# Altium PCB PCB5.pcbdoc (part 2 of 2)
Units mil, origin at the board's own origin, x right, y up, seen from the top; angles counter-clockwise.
Board outline 1951.69 x 1930.99 mil, 2 copper layers (Top Layer, Bottom Layer); 57 components, 38 nets, 209 pads, 95 vias.
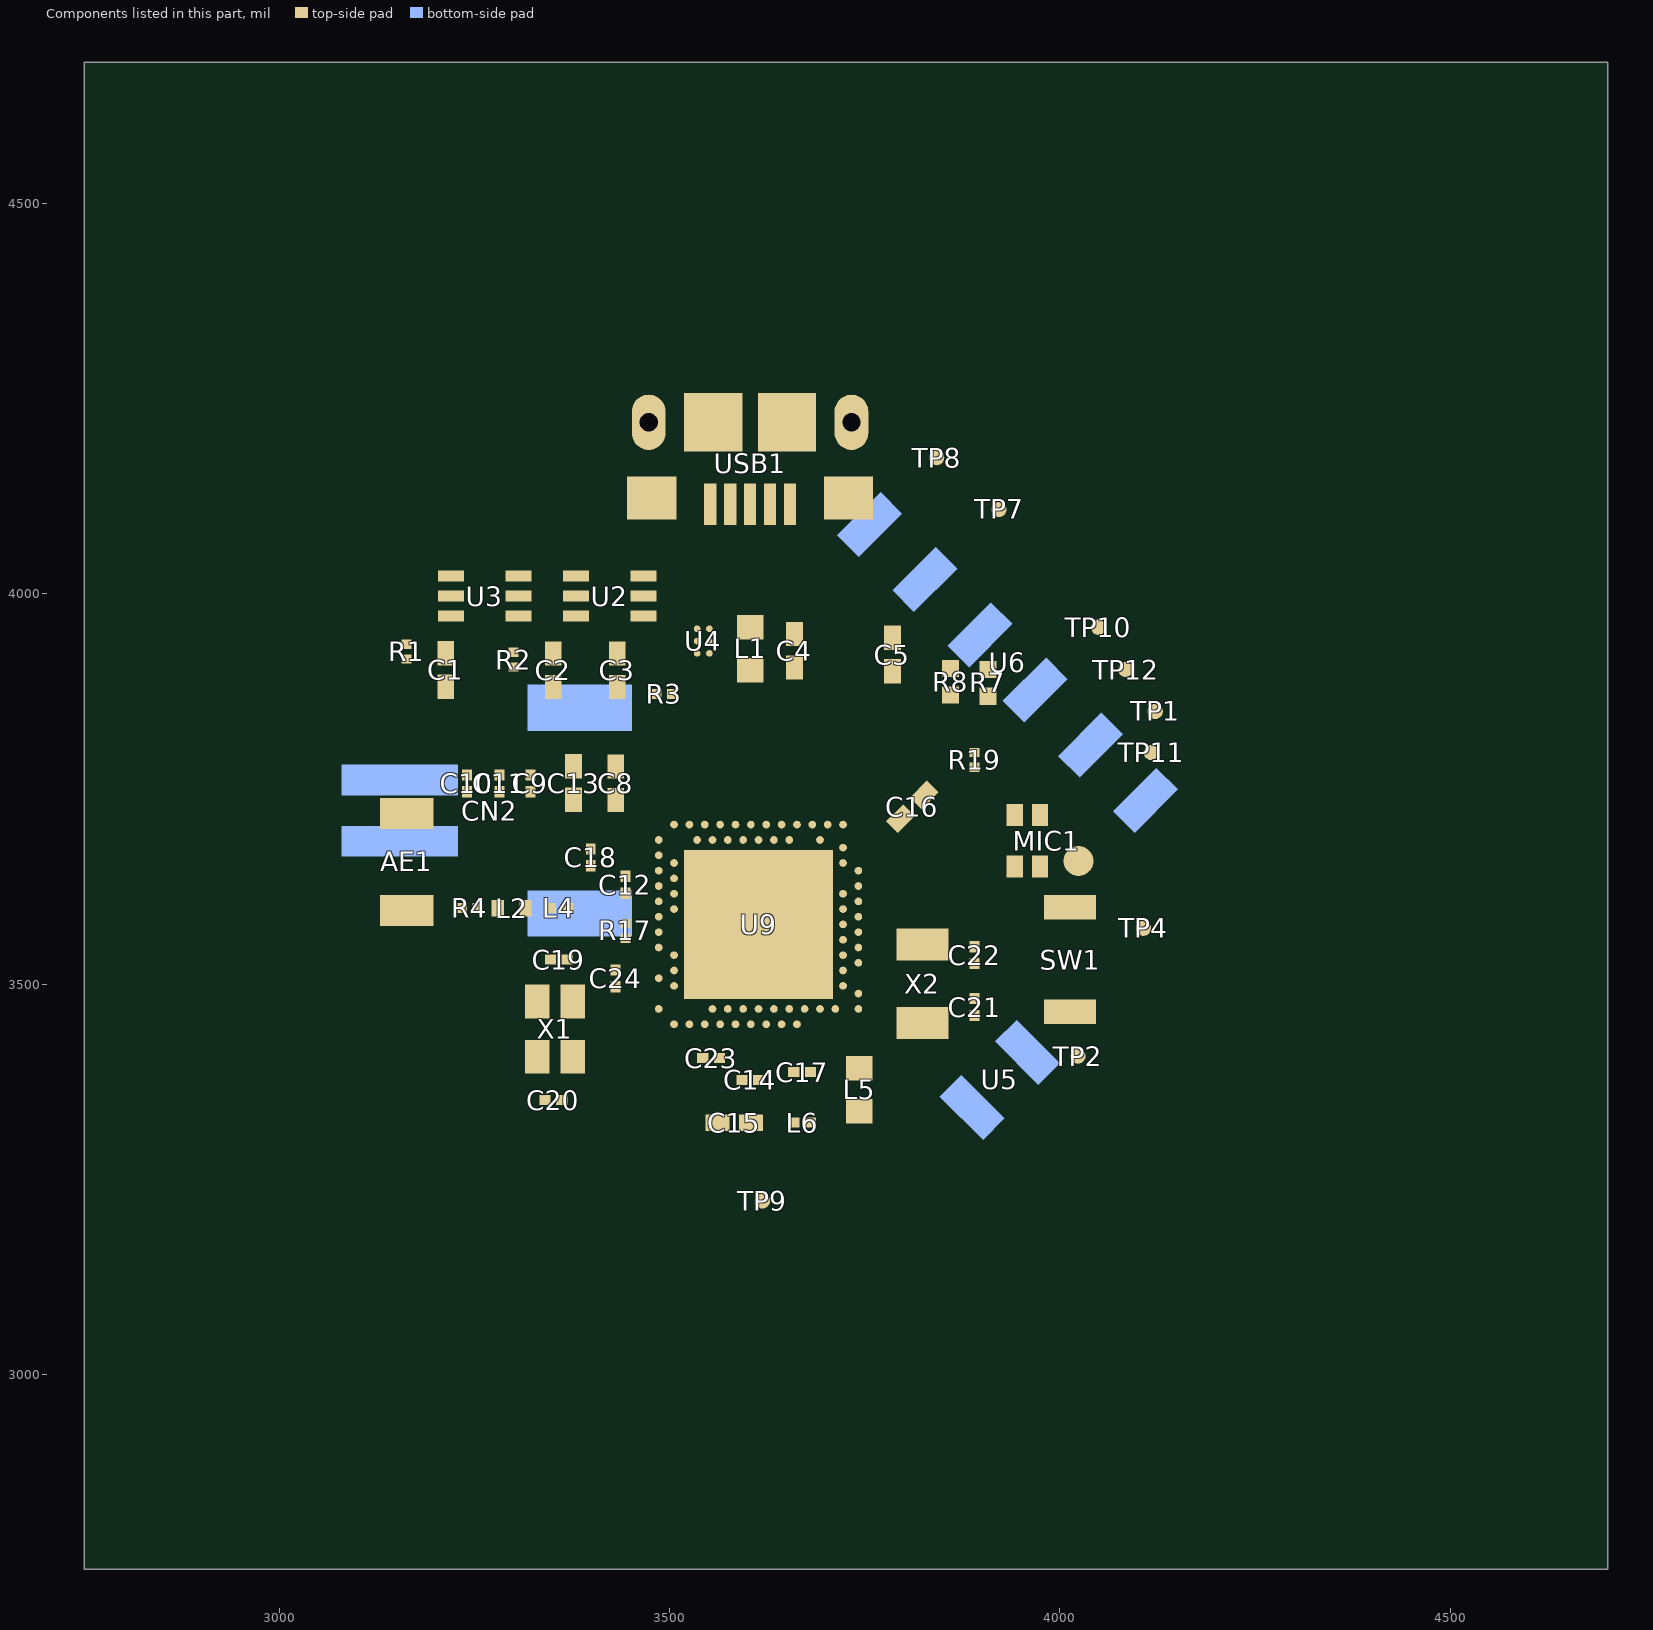
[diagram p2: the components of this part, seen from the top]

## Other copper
Top Layer:
  region net VBUS: 3651.17,4079.14 3657.08,4079.14 cw(c3668.15,4079.14) 3661.51,4088 3646.74,4088 cw(c3640.1,4079.14)
  region net $1N2608: 3443.52,4024.83 3443.52,4020.83 cw(c3443.52,4013.33) 3449.52,4017.83 3449.52,4027.83 cw(c3443.52,4032.33)
  region net $1N2608: 3304.25,3958.76 3308.25,3958.76 cw(c3315.75,3958.76) 3311.25,3964.76 3301.25,3964.76 cw(c3296.75,3958.76)
  region net $1N15802: 3285.28,4017.41 3285.28,4011.75 cw(c3295.74,4001.29) 3293.71,4015.94 3289.52,4025.89 cw(c3274.67,4028.01)
  region net $1N15802: 3175.32,3933.57 3175.32,3937.57 cw(c3175.32,3945.07) 3169.32,3940.57 3169.32,3930.57 cw(c3175.32,3926.07)
  region net $1N15802: 3227.82,3936.11 3227.82,3941.77 cw(c3222.46,3947.12) 3221.43,3939.62 3223.57,3927.63 cw(c3238.42,3925.5)
  region net $1N2608: 3312.3,3923.33 3312.3,3927.33 cw(c3312.3,3934.83) 3306.3,3930.33 3306.3,3920.33 cw(c3312.3,3915.83)
  region net $1N2608: 3307.67,3930.26 3304.84,3933.08 cw(c3300.18,3937.74) 3298.81,3931.3 3306.3,3924.64 cw(c3311.61,3926.32)
  region net $1N2608: 3367.56,3920.24 3367.56,3924.24 cw(c3367.56,3931.74) 3361.56,3927.24 3361.56,3917.24 cw(c3367.56,3912.74)
  region net $1N2608: 3334.3,3927.33 3334.3,3923.33 cw(c3334.3,3915.83) 3340.3,3920.33 3340.3,3930.33 cw(c3334.3,3934.83)
  region: 3449.57,3921.7 3449.57,3925.7 cw(c3449.57,3933.2) 3443.57,3928.7 3443.57,3918.7 cw(c3449.57,3914.2)
  region net +3V3: 3626.98,3899.79 3626.98,3904.48 cw(c3626.98,3913.26) 3619.95,3907.99 3619.95,3896.28 cw(c3626.98,3891.01)
  region net +3V3: 3585.11,3924.15 3579.67,3921.23 cw(c3564.01,3905.57) 3585.94,3908.7 3597.64,3917.88 cw(c3600.77,3939.81)
  region net LX: 3585.78,3977.23 3581.69,3975.67 cw(c3571.09,3965.06) 3585.94,3967.18 3594.27,3972.99 cw(c3596.39,3987.84)
  region net +3V3: 3642.18,3904.48 3642.18,3899.79 cw(c3642.18,3891.01) 3649.21,3896.28 3649.21,3907.99 cw(c3642.18,3913.26)
  region net +3V3: 3679.33,3902.83 3679.33,3908.74 cw(c3679.33,3919.81) 3670.47,3913.17 3670.47,3898.4 cw(c3679.33,3891.76)
  region net $1N3382: 3203.39,3595.24 3203.39,3599.24 cw(c3203.39,3606.74) 3197.39,3602.24 3197.39,3592.24 cw(c3203.39,3587.74)
  region net $1N3382: 3222.07,3599.24 3222.07,3595.24 cw(c3222.07,3587.74) 3228.07,3592.24 3228.07,3602.24 cw(c3222.07,3606.74)
  region net $1N5000: 3265.03,3595.24 3265.03,3599.24 cw(c3265.03,3606.74) 3259.03,3602.24 3259.03,3592.24 cw(c3265.03,3587.74)
  region net $1N5000: 3265.81,3599.24 3265.81,3595.24 cw(c3265.81,3587.74) 3271.81,3592.24 3271.81,3602.24 cw(c3265.81,3606.74)
  region net ANT: 3328.99,3595.24 3328.99,3599.24 cw(c3328.99,3606.74) 3322.99,3602.24 3322.99,3592.24 cw(c3328.99,3587.74)
  region net +3V3: 3890.12,3906.81 3890.12,3902.13 cw(c3890.12,3893.34) 3897.15,3898.61 3897.15,3910.33 cw(c3890.12,3915.6)
  region net +3V3: 3920.57,3887 3923.38,3890.81 cw(c3935.8,3903.24) 3918.41,3900.75 3910.64,3891.96 cw(c3908.15,3874.57)
  region net VDDH: 3842.11,3872.73 3842.11,3868.05 cw(c3842.11,3859.26) 3849.14,3864.53 3849.14,3876.25 cw(c3842.11,3881.52)
  region net +3V3: 3862.11,3920.42 3857.42,3920.42 cw(c3852.37,3920.42) 3853.91,3915.61 3865.62,3915.61 cw(c3867.17,3920.42)
  region net +3V3: 3877.42,3902.13 3877.42,3906.81 cw(c3877.42,3915.6) 3870.4,3910.33 3870.4,3898.61 cw(c3877.42,3893.34)
  region net VDD_NRF: 3450.15,3774.29 3450.15,3780.2 cw(c3450.15,3791.27) 3441.3,3784.63 3441.3,3769.86 cw(c3450.15,3763.22)
  region net VDD_NRF: 3411.18,3781.66 3411.18,3775.75 cw(c3411.18,3764.68) 3420.04,3771.32 3420.04,3786.09 cw(c3411.18,3792.73)
  region net VDD_NRF: 3306.29,3771 3306.29,3765.09 cw(c3306.29,3753.65) 3315.15,3760.89 3315.15,3775.2 cw(c3306.29,3782.44)
  region net VDD_NRF: 3334.16,3776.51 3330.1,3780.79 cw(c3316.65,3794.24) 3318.34,3775.3 3327.9,3763.98 cw(c3349.82,3760.85)
  region net VDD_NRF: 3255.19,3765.09 3255.19,3771 cw(c3255.19,3782.27) 3246.33,3775.3 3246.33,3760.79 cw(c3255.19,3753.82)
  region net VDD_NRF: 3266.37,3771 3266.37,3765.09 cw(c3266.37,3753.65) 3275.23,3760.89 3275.23,3775.2 cw(c3266.37,3782.44)
  region net VDD_NRF: 3296.84,3765.09 3296.84,3771 cw(c3296.84,3782.27) 3287.99,3775.3 3287.99,3760.79 cw(c3296.84,3753.82)
  region net NRF_ANT: 3441.14,3546.75 3445.14,3546.75 cw(c3452.64,3546.75) 3448.14,3552.75 3438.14,3552.75 cw(c3433.64,3546.75)
  region net $1N39111: 3380.3,3605.91 3376.6,3607.86 cw(c3365.99,3618.47) 3368.11,3603.62 3376.06,3597.43 cw(c3390.91,3595.3)
  region net ANT: 3333.96,3599.24 3333.96,3595.24 cw(c3333.96,3587.74) 3339.96,3592.24 3339.96,3602.24 cw(c3333.96,3606.74)
  region net $1N39111: 3452.41,3604.95 3453.76,3609.25 cw(c3464.37,3619.86) 3449.52,3617.74 3443.93,3609.19 cw(c3441.8,3594.34)
  region net $1N39111: 3430.77,3618.44 3430.77,3614.44 cw(c3430.77,3606.94) 3436.77,3611.44 3436.77,3621.44 cw(c3430.77,3625.94)
  region net VBUS: 3770.22,3888.9 3773.53,3885.59 cw(c3775.69,3883.43) 3778.14,3885.23 3774.79,3898.44 cw(c3758.97,3900.15)
  region net VDD_NRF: 3357.2,3781.66 3357.2,3775.75 cw(c3357.2,3764.68) 3366.05,3771.32 3366.05,3786.09 cw(c3357.2,3792.73)
  region net VDD_NRF: 3396.17,3775.75 3396.17,3781.66 cw(c3396.17,3792.73) 3387.31,3786.09 3387.31,3771.32 cw(c3396.17,3764.68)
  region net $1N39307: 3693.59,3320.4 3693.59,3324.4 cw(c3693.59,3331.9) 3687.59,3327.4 3687.59,3317.4 cw(c3693.59,3312.9)
  region net DEC46: 3590.54,3364.87 3594.54,3364.87 cw(c3602.04,3364.87) 3597.54,3370.87 3587.54,3370.87 cw(c3583.04,3364.87)
  region net DEC46: 3594.54,3386.84 3590.54,3386.84 cw(c3587.31,3386.84) 3587.54,3383.62 3597.54,3383.62 cw(c3597.76,3386.84)
  region net DEC46: 3549.07,3337.12 3543.41,3337.12 cw(c3538.06,3331.76) 3545.56,3330.73 3557.56,3332.87 cw(c3559.68,3347.72)
  region net DEC46: 3578.82,3337.12 3573.16,3337.12 cw(c3562.55,3347.72) 3564.67,3332.87 3576.67,3330.73 cw(c3584.17,3331.76)
  region net $1N38769: 3779.07,3698.1 3781.9,3695.27 cw(c3787.21,3689.97) 3788.27,3697.4 3781.2,3704.47 cw(c3773.77,3703.41)
  region net DEC1: 3692.94,3385.24 3692.94,3389.24 cw(c3692.94,3395.53) 3687.59,3392.24 3687.59,3382.24 cw(c3692.94,3378.96)
  region net XC1: 3335.71,3522.78 3339.42,3520.82 cw(c3350.02,3510.22) 3347.9,3525.07 3339.96,3531.26 cw(c3325.11,3533.38)
  region net XC2: 3373.21,3360.11 3369.5,3362.06 cw(c3358.9,3372.67) 3361.02,3357.82 3368.97,3351.63 cw(c3383.81,3349.5)
  region net XL1: 3880.15,3452.05 3882.61,3448.85 cw(c3891.77,3439.7) 3890.59,3452.59 3884.4,3460.54 cw(c3869.55,3462.66)
  region net XL2: 3878.4,3550.04 3878.4,3546.04 cw(c3878.4,3538.54) 3884.4,3543.04 3884.4,3553.04 cw(c3878.4,3557.54)
  region net PDM_DATA: 4119.98,3836.01 4123.98,3836.01 4124.01,3836.73 4124.1,3837.35 4124.24,3837.9 4124.44,3838.38 4124.68,3838.8 4124.97,3839.18 4125.3,3839.52 4125.66,3839.84 4126.92,3840.77 4127.86,3841.48 4128.35,3841.9 4128.85,3842.37 4129.36,3842.9 4114.59,3842.9 4115.1,3842.37 4115.6,3841.9 4116.57,3841.11 4117.9,3840.15 4118.29,3839.84 4118.66,3839.52 4118.98,3839.18 4119.27,3838.8 4119.51,3838.38 4119.71,3837.9 4119.85,3837.35 4119.94,3836.73
  region net GPIO2: 4093.58,3573.52 4093.58,3569.52 4094.29,3569.49 4094.91,3569.4 4095.46,3569.25 4095.94,3569.06 4096.36,3568.81 4096.74,3568.53 4097.08,3568.2 4097.4,3567.84 4098.33,3566.58 4099.05,3565.63 4099.46,3565.14 4099.93,3564.64 4100.47,3564.14 4100.47,3578.9 4099.93,3578.4 4099.46,3577.9 4098.67,3576.93 4097.71,3575.6 4097.4,3575.2 4097.08,3574.84 4096.74,3574.51 4096.36,3574.23 4095.94,3573.98 4095.46,3573.79 4094.91,3573.64 4094.29,3573.55
  region net SWDCLK: 3911.09,4100.1 3913.91,4097.27 3914.44,4097.75 3914.95,4098.13 3915.44,4098.41 3915.91,4098.61 3916.38,4098.74 3916.85,4098.8 3917.33,4098.81 3917.81,4098.78 3919.36,4098.55 3920.53,4098.39 3921.17,4098.33 3921.86,4098.31 3922.59,4098.33 3912.15,4108.77 3912.13,4108.04 3912.15,4107.35 3912.28,4106.11 3912.54,4104.49 3912.6,4103.99 3912.63,4103.51 3912.62,4103.04 3912.56,4102.57 3912.43,4102.1 3912.23,4101.62 3911.95,4101.13 3911.57,4100.62
  region net SWDIO: 3831.09,4166.58 3833.92,4163.75 3834.44,4164.23 3834.95,4164.61 3835.44,4164.89 3835.92,4165.09 3836.39,4165.22 3836.86,4165.28 3837.33,4165.29 3837.81,4165.26 3839.36,4165.03 3840.53,4164.87 3841.17,4164.81 3841.86,4164.79 3842.6,4164.81 3832.16,4175.25 3832.13,4174.52 3832.15,4173.83 3832.29,4172.59 3832.55,4170.97 3832.61,4170.47 3832.64,4169.99 3832.62,4169.52 3832.56,4169.05 3832.43,4168.57 3832.23,4168.1 3831.95,4167.61 3831.57,4167.1
  region net VDD_NRF: 3605.3,3225.2 3605.3,3219.29 3605.9,3219.27 3606.45,3219.19 3606.96,3219.07 3607.43,3218.91 3607.87,3218.71 3608.29,3218.47 3608.68,3218.21 3609.06,3217.91 3609.79,3217.24 3611.73,3215.28 3612.19,3214.86 3612.19,3229.63 3610.91,3228.4 3609.42,3226.91 3609.06,3226.58 3608.68,3226.28 3608.29,3226.01 3607.87,3225.78 3607.43,3225.58 3606.96,3225.42 3606.45,3225.3 3605.9,3225.22
  region net VDD_NRF: 3632.1,3219.29 3632.1,3225.2 3631.5,3225.22 3630.94,3225.3 3630.43,3225.42 3629.96,3225.58 3629.52,3225.78 3629.11,3226.01 3628.72,3226.28 3628.34,3226.58 3627.61,3227.25 3625.66,3229.21 3625.21,3229.63 3625.21,3214.86 3626.49,3216.09 3627.97,3217.58 3628.34,3217.91 3628.72,3218.21 3629.11,3218.47 3629.52,3218.71 3629.96,3218.91 3630.43,3219.07 3630.94,3219.19 3631.5,3219.27
  region net RESET: 4038.46,3949.18 4041.29,3946.35 4041.81,3946.84 4042.32,3947.22 4042.81,3947.5 4043.28,3947.7 4043.76,3947.83 4044.23,3947.89 4044.7,3947.9 4045.18,3947.87 4046.73,3947.64 4047.9,3947.47 4048.54,3947.42 4049.23,3947.4 4049.96,3947.42 4039.52,3957.86 4039.5,3957.13 4039.52,3956.44 4039.65,3955.2 4039.91,3953.57 4039.97,3953.08 4040,3952.6 4039.99,3952.12 4039.93,3951.65 4039.8,3951.18 4039.6,3950.7 4039.32,3950.22 4038.94,3949.71
  region net PDM_CLK: 4073.14,3895.04 4075.97,3892.21 4076.5,3892.69 4077,3893.07 4077.49,3893.36 4077.97,3893.55 4078.44,3893.68 4078.91,3893.74 4079.38,3893.76 4079.87,3893.73 4081.42,3893.5 4082.59,3893.33 4083.23,3893.28 4083.91,3893.25 4084.65,3893.28 4074.21,3903.72 4074.19,3902.98 4074.21,3902.3 4074.34,3901.05 4074.6,3899.43 4074.66,3898.93 4074.69,3898.45 4074.68,3897.98 4074.61,3897.51 4074.49,3897.04 4074.29,3896.56 4074,3896.07 4073.63,3895.57
  region net PDM_DATA: 3925.82,3652.8 3925.82,3648.8 cw(c3925.82,3641.3) 3931.82,3645.8 3931.82,3655.8 cw(c3925.82,3660.3)
  region net PDM_CLK: 3970.94,3697.24 3974.94,3697.24 cw(c3981.06,3697.24) 3977.94,3702.51 3967.94,3702.51 cw(c3964.83,3697.24)
  region net MIC_EN: 3936.04,3735.29 3930.39,3735.29 cw(c3926.35,3731.26) 3931.82,3729.62 3944.53,3731.05 cw(c3946.65,3745.9)
  region: 3529.28,3925.7 3529.28,3921.7 3530.07,3921.63 3530.87,3921.42 3531.62,3921.09 3532.26,3920.64 3532.26,3927.02 3531.62,3926.54 3530.87,3926.12 3530.07,3925.82
  region: 3540.86,3921.83 3540.86,3925.83 3540.08,3925.93 3539.28,3926.18 3538.53,3926.56 3537.89,3927.02 3537.89,3920.64 3538.53,3921.11 3539.28,3921.49 3540.08,3921.74
  region: 3545.02,3925.83 3545.02,3921.83 3545.81,3921.74 3546.61,3921.49 3547.36,3921.11 3548,3920.64 3548,3927.02 3547.36,3926.56 3546.61,3926.18 3545.81,3925.93
  region net LX: 3529.28,3941.58 3529.28,3937.58 3530.07,3937.49 3530.87,3937.24 3531.62,3936.86 3532.26,3936.39 3532.26,3942.77 3531.62,3942.31 3530.87,3941.93 3530.07,3941.68
  region net +3V3: 3556.6,3936.63 3556.6,3942.54 3555.71,3942.45 3554.99,3942.32 3554.33,3942.36 3553.63,3942.77 3553.63,3936.39 3554.33,3936.81 3554.99,3936.85 3555.71,3936.72
  region net $1N2785: 3556.6,3953.33 3556.6,3957.33 3555.82,3957.43 3555.02,3957.68 3554.27,3958.06 3553.63,3958.52 3553.63,3952.14 3554.27,3952.61 3555.02,3952.99 3555.82,3953.24
  region net XL2: 3796,3525.75 3801.66,3525.75 cw(c3812.27,3515.14) 3810.15,3529.99 3796,3529.99 cw(c3793.88,3527.87)
  region net XL2: 3863.21,3546.04 3863.21,3550.04 cw(c3863.21,3557.54) 3857.21,3553.04 3857.21,3543.04 cw(c3863.21,3538.54)
  region net XL1: 3801.66,3475.18 3796,3475.18 cw(c3793.88,3473.06) 3796,3470.94 3810.15,3470.94 cw(c3812.27,3485.79)
  region net XL1: 3863.21,3448.27 3863.21,3452.27 cw(c3863.21,3459.77) 3857.21,3455.27 3857.21,3445.27 cw(c3863.21,3440.77)
  region net XC1: 3332.18,3505.33 3328.18,3505.33 cw(c3320.68,3505.33) 3325.18,3499.33 3335.18,3499.33 cw(c3339.68,3505.33)
  region net XC2: 3373.46,3379.16 3377.46,3379.16 cw(c3384.96,3379.16) 3380.46,3385.16 3370.46,3385.16 cw(c3365.96,3379.16)
  region net PIEZO_READ: 4009.54,3415.55 4009.54,3409.65 4010.17,3409.57 4010.74,3409.34 4011.26,3408.99 4011.73,3408.52 4012.17,3407.96 4012.57,3407.32 4013.32,3405.88 4014.74,3402.8 4015.12,3402.09 4015.53,3401.44 4015.96,3400.86 4016.43,3400.37 4016.43,3415.14 4015.82,3414.81 4015.03,3414.69 4014.13,3414.73 4013.16,3414.89 4010.31,3415.48
  region net MIC_EN: 3878.4,3779.73 3878.4,3775.73 cw(c3878.4,3768.23) 3884.4,3772.73 3884.4,3782.73 cw(c3878.4,3787.23)
  region net MIC_EN: 3898.16,3767.52 3901.39,3769.94 cw(c3912,3780.55) 3897.15,3778.43 3889.67,3771.77 cw(c3887.55,3756.92)
  region net $1N39479: 3562.56,3441.79 3566.56,3441.79 3566.71,3442.74 3567.09,3443.64 3567.63,3444.48 3568.26,3445.24 3560.87,3445.24 3561.49,3444.48 3562.04,3443.64 3562.42,3442.74
  region net VDD_NRF: 3738.77,3461.47 3744.68,3461.47 3744.67,3462.42 3744.72,3463.32 3744.94,3464.15 3745.42,3464.92 3738.03,3464.92 3738.51,3464.15 3738.73,3463.32 3738.78,3462.42
  region net DEC46: 3690.51,3461.47 3694.51,3461.47 3694.66,3462.42 3695.04,3463.32 3695.58,3464.16 3696.21,3464.92 3688.82,3464.92 3689.44,3464.16 3689.99,3463.32 3690.37,3462.42
  region net DEC1: 3735.57,3484.54 3738.4,3481.71 3739.17,3482.28 3740.08,3482.64 3741.05,3482.85 3742.03,3482.95 3736.81,3488.17 3736.71,3487.19 3736.5,3486.22 3736.14,3485.31
  region net XL1: 3728,3500.83 3725.17,3503.66 3724.43,3503.13 3723.59,3502.83 3722.68,3502.69 3721.74,3502.62 3726.96,3497.4 3727.03,3498.34 3727.17,3499.25 3727.47,3500.09
  region net DEC46: 3479.67,3504.22 3482.5,3501.39 3483.27,3501.96 3484.18,3502.32 3485.15,3502.53 3486.13,3502.63 3480.91,3507.85 3480.81,3506.87 3480.6,3505.9 3480.24,3504.99
  region net XL2: 3725.37,3511.24 3728.2,3514.07 3727.63,3514.84 3727.27,3515.75 3727.06,3516.72 3726.96,3517.7 3721.74,3512.48 3722.72,3512.38 3723.69,3512.17 3724.6,3511.81
  region net NRF_ANT: 3499.35,3533.75 3502.18,3530.92 3502.95,3531.49 3503.86,3531.85 3504.83,3532.06 3505.81,3532.16 3500.59,3537.38 3500.49,3536.4 3500.28,3535.43 3499.92,3534.52
  region net PDM_DATA: 3747.88,3609.3 3745.05,3612.13 3744.28,3611.56 3743.37,3611.2 3742.4,3610.99 3741.42,3610.89 3746.64,3605.67 3746.74,3606.64 3746.95,3607.62 3747.31,3608.53
  region net VDD_NRF: 3748.43,3642.39 3748.43,3648.3 3747.47,3648.29 3746.58,3648.34 3745.75,3648.56 3744.98,3649.04 3744.98,3641.65 3745.75,3642.13 3746.58,3642.35 3747.47,3642.4
  region net $1N38769: 3698.67,3688.04 3695.84,3690.87 3695.07,3690.3 3694.16,3689.94 3693.19,3689.73 3692.21,3689.63 3697.43,3684.41 3697.53,3685.38 3697.74,3686.36 3698.1,3687.27
  region net VBUS: 3725,3711.09 3719.09,3711.09 3719.1,3710.14 3719.05,3709.25 3718.83,3708.42 3718.35,3707.65 3725.74,3707.65 3725.26,3708.42 3725.04,3709.25 3724.99,3710.14
  region net VDD_NRF: 3606.89,3711.09 3600.98,3711.09 3600.99,3710.14 3600.94,3709.25 3600.72,3708.42 3600.24,3707.65 3607.63,3707.65 3607.15,3708.42 3606.93,3709.25 3606.88,3710.14
  region net VDD_NRF: 3502.85,3711.22 3498.68,3707.04 3499.36,3706.38 3499.95,3705.71 3500.39,3704.97 3500.59,3704.09 3505.81,3709.31 3504.93,3709.51 3504.19,3709.95 3503.52,3710.54
  region net $1N15802: 3299.55,4024.83 3299.55,4020.83 3300.5,4020.69 3301.4,4020.31 3302.24,4019.76 3303,4019.14 3303,4026.53 3302.24,4025.9 3301.4,4025.36 3300.5,4024.98
  region: 3439.64,3921.7 3439.64,3925.7 3438.7,3925.85 3437.8,3926.23 3436.96,3926.77 3436.2,3927.4 3436.2,3920.01 3436.96,3920.63 3437.8,3921.18 3438.7,3921.56
  region net LX: 3534.64,3985.24 3534.64,3989.24 3533.7,3989.39 3532.8,3989.77 3531.96,3990.31 3531.2,3990.94 3531.2,3983.55 3531.96,3984.17 3532.8,3984.72 3533.7,3985.1
  region net LX: 3516.27,3946.09 3519.1,3948.92 3518.53,3949.69 3518.17,3950.6 3517.96,3951.57 3517.86,3952.55 3512.64,3947.33 3513.61,3947.23 3514.59,3947.02 3515.5,3946.66
  region net $1N2785: 3561.24,3957.33 3561.24,3953.33 3561.85,3953.18 3562.35,3952.75 3562.77,3952.14 3563.14,3951.39 3563.83,3949.8 3564.23,3949.1 3564.69,3948.55 3564.69,3955.94 3563.93,3955.8 3563.08,3956.32 3562.18,3957
  region net VBUS: 3604.77,4014.89 3600.59,4019.07 3599.93,4018.39 3599.26,4017.8 3598.52,4017.36 3597.64,4017.16 3602.86,4011.94 3603.06,4012.82 3603.5,4013.56 3604.09,4014.23
  region net VBUS: 3341.12,4009.59 3345.29,4005.42 3345.96,4006.1 3346.63,4006.69 3347.37,4007.13 3348.25,4007.33 3343.03,4012.55 3342.83,4011.67 3342.39,4010.93 3341.79,4010.26
  region net VBUS: 3335.9,3963.94 3329.99,3963.94 3330,3962.99 3329.95,3962.1 3329.73,3961.27 3329.25,3960.5 3336.63,3960.5 3336.16,3961.27 3335.94,3962.1 3335.89,3962.99
  region net MIC_EN: 3749.1,3735.57 3746.27,3738.4 3745.5,3737.83 3744.59,3737.47 3743.61,3737.26 3742.64,3737.16 3747.86,3731.94 3747.96,3732.91 3748.17,3733.89 3748.53,3734.8
  region net DEC46: 3590.54,3370.54 3594.54,3370.54 3594.68,3371.49 3595.07,3372.39 3595.61,3373.23 3596.23,3373.99 3588.85,3373.99 3589.47,3373.23 3590.01,3372.39 3590.39,3371.49
  region net DEC46: 3594.54,3383.94 3590.54,3383.94 3590.39,3383 3590.01,3382.1 3589.47,3381.26 3588.85,3380.5 3596.23,3380.5 3595.61,3381.26 3595.07,3382.1 3594.68,3383
  region net XC1: 3341.06,3528.12 3343.88,3525.29 3344.65,3525.86 3345.56,3526.22 3346.54,3526.43 3347.52,3526.53 3342.3,3531.75 3342.2,3530.77 3341.98,3529.8 3341.62,3528.89
  region net XC2: 3373.46,3400.11 3377.46,3400.11 3377.61,3401.06 3377.99,3401.96 3378.53,3402.8 3379.15,3403.56 3371.77,3403.56 3372.39,3402.8 3372.93,3401.96 3373.31,3401.06
  region net BUTTON: 3801.27,3611.09 3804.1,3613.92 3803.53,3614.69 3803.17,3615.6 3802.96,3616.57 3802.86,3617.55 3797.64,3612.33 3798.61,3612.23 3799.59,3612.02 3800.5,3611.66
  region net +3V3: 3654.53,3903.79 3657.84,3900.48 3658.36,3900.83 3658.88,3900.92 3660.15,3900.87 3654.93,3906.09 3654.97,3904.83 3654.89,3904.31
  region net +3V3: 3666.54,3902.83 3666.54,3908.74 3665.59,3908.73 3664.69,3908.78 3663.86,3909 3663.09,3909.48 3663.09,3902.09 3663.86,3902.57 3664.69,3902.79 3665.59,3902.84
  region net +3V3: 3711.12,3909.59 3715.29,3905.42 3715.96,3906.1 3716.63,3906.69 3717.37,3907.13 3718.25,3907.33 3713.03,3912.55 3712.83,3911.67 3712.39,3910.93 3711.79,3910.26
  region net VDDH: 3745.29,3778.94 3740.6,3778.94 3740.49,3778.08 3740.18,3777.13 3739.75,3776.22 3739.25,3775.5 3746.63,3775.5 3746.14,3776.22 3745.71,3777.13 3745.4,3778.08
  region net +3V3: 3826.02,3950.85 3829.34,3954.16 3828.81,3954.85 3828.35,3955.75 3828.01,3956.7 3827.86,3957.55 3822.64,3952.33 3823.49,3952.18 3824.44,3951.84 3825.33,3951.38
  region net VDD_NRF: 3884.61,3793.9 3887.92,3790.59 3888.59,3791.08 3889.38,3791.4 3890.23,3791.58 3891.08,3791.67 3885.86,3796.89 3885.74,3796.1 3885.48,3795.28 3885.09,3794.53
  region net VDD_NRF: 3786.12,3669.59 3790.29,3665.42 3790.96,3666.1 3791.63,3666.69 3792.37,3667.13 3793.25,3667.33 3788.03,3672.55 3787.83,3671.67 3787.39,3670.93 3786.79,3670.26
  region net SWO: 3831.79,3888.92 3834.62,3886.09 3835.39,3886.66 3836.3,3887.02 3837.27,3887.23 3838.25,3887.33 3833.03,3892.55 3832.93,3891.57 3832.72,3890.6 3832.36,3889.69
  region net +3V3: 4032.31,3808.52 4032.31,3803.84 4033.17,3803.72 4034.13,3803.41 4035.04,3802.98 4035.75,3802.49 4035.75,3809.87 4035.04,3809.37 4034.13,3808.94 4033.17,3808.64
  region net RESET: 3749.1,3755.57 3746.27,3758.4 3745.5,3757.83 3744.59,3757.47 3743.61,3757.26 3742.64,3757.16 3747.86,3751.94 3747.96,3752.91 3748.17,3753.89 3748.53,3754.8
  region net RESET: 3916.24,3834.24 3916.24,3830.24 3917.19,3830.1 3918.09,3829.72 3918.93,3829.17 3919.69,3828.55 3919.69,3835.94 3918.93,3835.31 3918.09,3834.77 3917.19,3834.39
  region net PIEZO_READ: 3965,3409.65 3965,3415.55 3964.05,3415.55 3963.15,3415.6 3962.32,3415.81 3961.55,3416.29 3961.55,3408.91 3962.32,3409.39 3963.15,3409.6 3964.05,3409.65
  region net GPIO2: 4086.84,3569.52 4086.84,3573.52 4085.9,3573.67 4085,3574.05 4084.16,3574.59 4083.39,3575.21 4083.39,3567.83 4084.16,3568.45 4085,3568.99 4085.9,3569.38
  region net RESET: 3974.8,3879.87 3971.97,3882.69 3971.53,3882.33 3971.09,3882.08 3970.63,3881.93 3970.16,3881.85 3969.67,3881.82 3967.99,3881.8 3973.21,3876.58 3973.38,3877.43 3973.75,3878.34 3974.25,3879.19
  region net SWDCLK: 3832.13,4016.31 3832.13,4020.31 3831.41,4020.46 3831.01,4020.84 3830.67,4021.38 3830.13,4022 3830.13,4014.62 3830.67,4015.24 3831.01,4015.78 3831.41,4016.17
  region net SWDIO: 3783.3,4113.13 3780.47,4115.95 3779.67,4115.38 3778.75,4115.05 3777.77,4114.89 3776.74,4114.81 3781.96,4109.59 3782.08,4110.52 3782.34,4111.49 3782.75,4112.39
  region net PDM_CLK: 3970.94,3710.08 3974.94,3710.08 3975.33,3711 3976.24,3711.92 3977.31,3712.77 3978.14,3713.52 3970.76,3713.52 3971.24,3712.7 3971.26,3711.95 3971.07,3711.13
  region net PDM_CLK: 4059.21,3875.45 4056.38,3878.28 4055.58,3877.7 4054.66,3877.38 4053.67,3877.23 4052.64,3877.16 4057.86,3871.94 4057.98,3872.86 4058.25,3873.82 4058.67,3874.72
  region net PDM_DATA: 3935.39,3652.8 3935.39,3648.8 3936.34,3648.65 3937.24,3648.27 3938.08,3647.73 3938.84,3647.11 3938.84,3654.49 3938.08,3653.87 3937.24,3653.33 3936.34,3652.94
  region net PDM_DATA: 4032.63,3739.27 4029.8,3742.1 4029.03,3741.54 4028.12,3741.17 4027.14,3740.96 4026.17,3740.86 4031.39,3735.64 4031.49,3736.62 4031.7,3737.6 4032.06,3738.5
  region net VDD_NRF: 3564.64,3219.29 3564.64,3225.2 3563.69,3225.19 3562.8,3225.24 3561.97,3225.46 3561.2,3225.94 3561.2,3218.55 3561.97,3219.03 3562.8,3219.25 3563.69,3219.3
  region net VDD_NRF: 3583.15,3742.86 3587.33,3747.03 3586.65,3747.7 3586.06,3748.37 3585.62,3749.11 3585.42,3749.99 3580.2,3744.77 3581.08,3744.57 3581.82,3744.13 3582.49,3743.53
  region net VDD_NRF: 3573.8,3752.64 3573.8,3746.73 3574.76,3746.74 3575.65,3746.68 3576.48,3746.47 3577.25,3745.99 3577.25,3753.37 3576.48,3752.9 3575.65,3752.68 3574.76,3752.63
  region net VDD_NRF: 3809.64,3789.9 3809.64,3794.59 3808.78,3794.7 3807.83,3795.01 3806.92,3795.44 3806.2,3795.94 3806.2,3788.55 3806.92,3789.05 3807.83,3789.48 3808.78,3789.79
  region net VDD_NRF: 3915.59,3590.42 3919.77,3594.59 3919.09,3595.26 3918.5,3595.93 3918.06,3596.67 3917.86,3597.55 3912.64,3592.33 3913.52,3592.13 3914.26,3591.69 3914.93,3591.1
  region net BUTTON: 3909.62,3573.4 3906.79,3570.57 3907.36,3569.8 3907.72,3568.89 3907.93,3567.91 3908.03,3566.94 3913.25,3572.16 3912.27,3572.26 3911.3,3572.47 3910.39,3572.83
  region net VDD_NRF: 3935.9,3548.94 3929.99,3548.94 3930,3547.99 3929.95,3547.1 3929.73,3546.27 3929.25,3545.5 3936.63,3545.5 3936.16,3546.27 3935.94,3547.1 3935.89,3547.99
  region net VDD_NRF: 3891.55,3434.16 3894.86,3430.85 3895.55,3431.38 3896.45,3431.84 3897.39,3432.18 3898.25,3432.33 3893.03,3437.55 3892.87,3436.7 3892.54,3435.75 3892.08,3434.85
  region net VBUS: 3651.17,4077.28 3651.14,4076.54 3651.05,4075.74 3650.71,4074.01 3650.17,4072.19 3649.48,4070.35 3648.67,4068.55 3647.75,4066.89 3646.78,4065.43 3646.28,4064.8 3645.77,4064.25 3649.95,4060.07 3650.36,4060.44 3650.82,4060.76 3651.32,4061.03 3651.84,4061.25 3652.39,4061.42 3652.96,4061.54 3653.54,4061.61 3654.12,4061.64 3654.71,4061.61 3655.29,4061.54 3655.86,4061.42 3656.41,4061.25 3656.93,4061.03 3657.43,4060.76 3657.88,4060.44 3658.3,4060.07 3662.48,4064.25 3661.97,4064.8 3661.47,4065.43 3660.49,4066.89 3659.58,4068.55 3658.76,4070.35 3658.07,4072.19 3657.54,4074.01 3657.2,4075.74 3657.11,4076.54 3657.08,4077.28
  region net VDD_NRF: 3497.15,3753.86 3497.52,3753.44 3497.84,3752.99 3498.11,3752.49 3498.33,3751.97 3498.5,3751.42 3498.62,3750.85 3498.69,3750.27 3498.72,3749.68 3498.69,3749.1 3498.62,3748.52 3498.5,3747.95 3498.33,3747.4 3498.11,3746.87 3497.84,3746.38 3497.52,3745.92 3497.15,3745.51 3501.33,3741.33 3501.88,3741.84 3502.51,3742.34 3503.97,3743.31 3505.63,3744.23 3507.43,3745.04 3509.27,3745.73 3511.1,3746.27 3512.82,3746.61 3513.62,3746.7 3514.36,3746.73 3514.36,3752.64 3513.62,3752.67 3512.82,3752.76 3511.1,3753.1 3509.27,3753.63 3507.43,3754.32 3505.63,3755.14 3503.97,3756.05 3502.51,3757.03 3501.88,3757.53 3501.33,3758.03
  region net VBUS: 3741.49,3889.59 3740.92,3889.62 3740.36,3889.73 3739.83,3889.89 3739.31,3890.12 3738.82,3890.4 3738.36,3890.73 3737.93,3891.11 3737.53,3891.53 3737.17,3891.98 3736.85,3892.47 3736.57,3892.98 3736.33,3893.52 3736.15,3894.07 3736.01,3894.64 3735.93,3895.21 3735.9,3895.79 3729.99,3895.79 3729.95,3894.96 3729.85,3894.12 3729.68,3893.28 3729.45,3892.44 3729.17,3891.61 3728.83,3890.78 3728.03,3889.16 3727.08,3887.6 3726.02,3886.12 3724.88,3884.75 3723.71,3883.5 3727.89,3879.32 3728.46,3879.85 3729.12,3880.38 3729.85,3880.89 3731.49,3881.88 3733.3,3882.77 3735.21,3883.55 3737.13,3884.18 3738.99,3884.63 3739.87,3884.78 3740.71,3884.87 3741.49,3884.9
  region net VDD_NRF: 3784.35,3398.03 3784.5,3398.78 3784.89,3399.35 3785.43,3399.58 3786,3399.32 3783.48,3405.16 3773.04,3411.42 3773.57,3410.85 3774.09,3410.2 3774.59,3409.48 3775.55,3407.87 3776.41,3406.09 3777.16,3404.22 3777.76,3402.33 3778.18,3400.5 3778.32,3399.63 3778.41,3398.8 3778.44,3398.03
Bottom Layer:
  region net +BATT: 3235.95,3680.53 3235.95,3685.22 cw(c3235.95,3694) 3228.92,3688.73 3228.92,3677.02 cw(c3235.95,3671.75)
  region net PIEZO_READ: 3918.65,3415.55 3924.55,3409.65 cw(c3924.55,3387.5) 3937.84,3405.22 3923.08,3419.98 cw(c3918.65,3419.98)
  region net SWDIO: 3739.42,4108.6 3736.59,4105.77 cw(c3731.29,4100.47) 3738.71,4099.4 3745.78,4106.48 cw(c3744.72,4113.9)
  region net SWDCLK: 3790.2,4015.47 3786.2,4011.47 cw(c3786.2,4008.47) 3789.2,4008.47 3799.2,4018.47 cw(c3790.2,4030.47)
  region net SWO: 3861.95,3919.08 3864.78,3916.25 cw(c3870.08,3910.95) 3871.14,3918.37 3864.07,3925.44 cw(c3856.64,3924.38)
  region net RESET: 3934.8,3846.22 3937.63,3843.39 cw(c3942.94,3838.09) 3944,3845.51 3936.92,3852.59 cw(c3929.5,3851.53)
  region: 3226.33,3969.65 3226.33,3973.65 3225.39,3973.8 3224.49,3974.18 3223.65,3974.72 3222.89,3975.35 3222.89,3967.96 3223.65,3968.58 3224.49,3969.13 3225.39,3969.51
  region: 3372.93,3973.65 3372.93,3969.65 3373.88,3969.51 3374.78,3969.13 3375.62,3968.58 3376.38,3967.96 3376.38,3975.35 3375.62,3974.72 3374.78,3974.18 3373.88,3973.8
  region: 3384.99,3969.65 3384.99,3973.65 3384.26,3973.8 3383.82,3974.18 3383.44,3974.72 3382.89,3975.35 3382.89,3967.96 3383.44,3968.58 3383.82,3969.13 3384.26,3969.51
  region net $1N15802: 3310.13,4017.23 3312.96,4020.06 3312.33,4020.73 3311.77,4021.47 3311.36,4022.27 3311.17,4023.14 3305.95,4017.92 3306.61,4017.91 3307.74,4018 3308.24,4018.03 3308.72,4018 3309.18,4017.88 3309.64,4017.64
  region net $1N15802: 3462.93,3977.81 3460.1,3974.98 3460.67,3974.21 3461.03,3973.3 3461.24,3972.32 3461.34,3971.35 3466.56,3976.57 3465.58,3976.67 3464.61,3976.88 3463.7,3977.24
  region: 3429.62,3929.86 3426.79,3927.03 3427.36,3926.26 3427.72,3925.35 3427.93,3924.37 3428.03,3923.4 3433.25,3928.62 3432.27,3928.72 3431.3,3928.93 3430.39,3929.29
  region net LX: 3521.79,3983.92 3524.62,3981.09 3525.39,3981.66 3526.3,3982.02 3527.27,3982.23 3528.25,3982.33 3523.03,3987.55 3522.93,3986.57 3522.72,3985.6 3522.36,3984.69
  region net LX: 3514.94,3958.94 3510.94,3958.94 3510.8,3958 3510.42,3957.1 3509.87,3956.26 3509.25,3955.5 3516.63,3955.5 3516.01,3956.26 3515.47,3957.1 3515.09,3958
  region net $1N2785: 3571.27,3946.09 3574.1,3948.92 3573.53,3949.69 3573.17,3950.6 3572.96,3951.57 3572.86,3952.55 3567.64,3947.33 3568.61,3947.23 3569.59,3947.02 3570.5,3946.66
  region net $1N2785: 3509.15,3869.97 3509.15,3873.97 3508.21,3874.12 3507.31,3874.5 3506.47,3875.04 3505.71,3875.66 3505.71,3868.28 3506.47,3868.9 3507.31,3869.44 3508.21,3869.83
  region net VBUS: 3591.24,4015.2 3591.24,4009.29 3592.19,4009.3 3593.09,4009.25 3593.92,4009.03 3594.69,4008.55 3594.69,4015.94 3593.92,4015.46 3593.09,4015.24 3592.19,4015.19
  region net VBUS: 3354.64,4009.29 3354.64,4015.2 3353.69,4015.19 3352.8,4015.24 3351.97,4015.46 3351.2,4015.94 3351.2,4008.55 3351.97,4009.03 3352.8,4009.25 3353.69,4009.3
  region net VBUS: 3306.74,3909.61 3302.57,3913.79 3301.9,3913.11 3301.23,3912.52 3300.49,3912.08 3299.61,3911.88 3304.83,3906.66 3305.03,3907.54 3305.47,3908.28 3306.07,3908.95
  region net VBUS: 3326.12,3954.59 3330.29,3950.42 3330.96,3951.1 3331.63,3951.69 3332.37,3952.13 3333.25,3952.33 3328.03,3957.55 3327.83,3956.67 3327.39,3955.93 3326.79,3955.26
  region net MIC_EN: 3649.46,3707.72 3646.63,3710.55 3645.86,3709.99 3644.95,3709.62 3643.98,3709.41 3643,3709.31 3648.22,3704.09 3648.32,3705.07 3648.53,3706.05 3648.89,3706.95
  region net MIC_EN: 3736.24,3734.24 3736.24,3730.24 3737.19,3730.1 3738.09,3729.72 3738.93,3729.17 3739.69,3728.55 3739.69,3735.94 3738.93,3735.31 3738.09,3734.77 3737.19,3734.39
  region net PDM_CLK: 3728.74,3594.13 3728.74,3598.13 3727.8,3598.28 3726.9,3598.66 3726.06,3599.2 3725.3,3599.83 3725.3,3592.44 3726.06,3593.06 3726.9,3593.61 3727.8,3593.99
  region net DEC46: 3595.86,3371.09 3598.69,3373.92 3598.13,3374.69 3597.76,3375.6 3597.55,3376.57 3597.45,3377.55 3592.23,3372.33 3593.21,3372.23 3594.18,3372.02 3595.09,3371.66
  region net DEC46: 3652.03,3324.4 3652.03,3320.4 3652.98,3320.25 3653.87,3319.87 3654.71,3319.33 3655.48,3318.71 3655.48,3326.09 3654.71,3325.47 3653.87,3324.93 3652.98,3324.54
  region net XC1: 3479.12,3470.17 3479.12,3466.17 3480.07,3466.03 3480.97,3465.65 3481.81,3465.1 3482.57,3464.48 3482.57,3471.87 3481.81,3471.24 3480.97,3470.7 3480.07,3470.32
  region net XC1: 3350.53,3525.29 3353.36,3528.12 3352.8,3528.89 3352.43,3529.8 3352.22,3530.77 3352.12,3531.75 3346.9,3526.53 3347.88,3526.43 3348.85,3526.22 3349.76,3525.86
  region net XC2: 3499.35,3445.18 3502.18,3442.35 3502.95,3442.91 3503.86,3443.28 3504.84,3443.49 3505.81,3443.59 3500.6,3448.81 3500.49,3447.83 3500.28,3446.85 3499.92,3445.95
  region net XC2: 3382.16,3404.81 3382.16,3408.81 3381.22,3408.96 3380.32,3409.34 3379.48,3409.88 3378.72,3410.51 3378.72,3403.12 3379.48,3403.74 3380.32,3404.29 3381.22,3404.67
  region net SWDCLK: 3626.53,4107.87 3630.53,4107.87 3630.68,4108.81 3631.06,4109.71 3631.6,4110.55 3632.22,4111.32 3624.84,4111.32 3625.46,4110.55 3626.01,4109.71 3626.39,4108.81
  region net SWDIO: 3600.94,4107.87 3604.94,4107.87 3605.09,4108.81 3605.47,4109.71 3606.01,4110.55 3606.63,4111.32 3599.25,4111.32 3599.87,4110.55 3600.42,4109.71 3600.8,4108.81
  region net SWDIO: 3604.94,4121.27 3600.94,4121.27 3600.8,4120.33 3600.42,4119.43 3599.87,4118.59 3599.25,4117.83 3606.63,4117.83 3606.01,4118.59 3605.47,4119.43 3605.09,4120.33
  region net SWDIO: 3487.82,3691.41 3483.82,3691.41 3483.68,3690.47 3483.3,3689.57 3482.75,3688.73 3482.13,3687.97 3489.52,3687.97 3488.89,3688.73 3488.35,3689.57 3487.97,3690.47
  region net SWDCLK: 3491.98,3668.35 3489.15,3671.18 3488.38,3670.61 3487.47,3670.25 3486.5,3670.04 3485.52,3669.94 3490.74,3664.72 3490.84,3665.69 3491.05,3666.67 3491.41,3667.58
  region net BUTTON: 3728.74,3615.24 3728.74,3619.24 3728.19,3619.21 3727.27,3619.05 3726.87,3618.98 3726.49,3618.97 3726.11,3619.03 3725.72,3619.2 3725.3,3619.51 3725.3,3612.12 3725.65,3612.48 3726.91,3613.98 3727.37,3614.46 3727.83,3614.87 3728.29,3615.14
  region net BUTTON: 3791.24,3619.24 3791.24,3615.24 3792.19,3615.1 3793.09,3614.72 3793.93,3614.17 3794.69,3613.55 3794.69,3620.94 3793.93,3620.31 3793.09,3619.77 3792.19,3619.39
  region net $1N39540: 3498.8,3498.63 3498.8,3494.63 3500.66,3494.66 3501.47,3494.49 3502.25,3494.01 3502.25,3501.4 3501.74,3500.88 3501.34,3500.38 3500.72,3499.49 3500.4,3499.14 3500.01,3498.86 3499.49,3498.69
  region net $1N39540: 3437.37,3494.63 3437.37,3498.63 3436.42,3498.77 3435.52,3499.15 3434.68,3499.7 3433.92,3500.32 3433.92,3492.93 3434.68,3493.56 3435.52,3494.1 3436.42,3494.48
  region net $1N38954: 3405.44,3648.43 3405.44,3652.43 3404.5,3652.58 3403.6,3652.96 3402.76,3653.5 3402,3654.12 3402,3646.74 3402.76,3647.36 3403.6,3647.9 3404.5,3648.29
  region net +3V3: 3720.9,3918.94 3714.99,3918.94 3715,3917.99 3714.95,3917.1 3714.73,3916.27 3714.25,3915.5 3721.63,3915.5 3721.16,3916.27 3720.94,3917.1 3720.89,3917.99
  region net VDDH: 3745.59,3765.42 3749.77,3769.59 3749.09,3770.26 3748.5,3770.93 3748.06,3771.67 3747.86,3772.55 3742.64,3767.33 3743.52,3767.13 3744.26,3766.69 3744.93,3766.1
  region net VDDH: 3728.87,3657.83 3724.69,3662.01 3724.03,3661.33 3723.36,3660.74 3722.62,3660.3 3721.74,3660.1 3726.96,3654.88 3727.16,3655.76 3727.6,3656.5 3728.19,3657.17
  region net PIEZO_READ: 3748.42,3543.98 3748.42,3549.88 3747.47,3549.88 3746.57,3549.93 3745.74,3550.14 3744.97,3550.62 3744.97,3543.24 3745.74,3543.72 3746.57,3543.93 3747.47,3543.98
  region net DCC: 3710.19,3461.47 3714.19,3461.47 3714.34,3462.42 3714.72,3463.32 3715.26,3464.16 3715.89,3464.92 3708.5,3464.92 3709.12,3464.16 3709.67,3463.32 3710.05,3462.42
  region net DCC: 3739.67,3398.57 3736.84,3395.74 3737.4,3394.97 3737.77,3394.06 3737.98,3393.08 3738.08,3392.11 3743.3,3397.33 3742.32,3397.43 3741.34,3397.64 3740.44,3398
  region net +3V3: 3820.29,3964.07 3816.12,3959.89 3816.79,3959.23 3817.39,3958.56 3817.83,3957.82 3818.03,3956.94 3823.25,3962.16 3822.37,3962.36 3821.63,3962.8 3820.96,3963.39
  region net VDD_NRF: 3905.44,3862.32 3910.12,3862.32 3910.24,3863.18 3910.55,3864.14 3910.98,3865.05 3911.47,3865.76 3904.09,3865.76 3904.59,3865.05 3905.02,3864.14 3905.32,3863.18
  region net VDD_NRF: 3887.82,3789.88 3893.73,3789.88 3893.72,3790.83 3893.77,3791.72 3893.99,3792.55 3894.47,3793.32 3887.08,3793.32 3887.56,3792.55 3887.78,3791.72 3887.83,3790.83
  region net VDD_NRF: 3897.17,3799.66 3893.86,3802.97 3893.16,3802.44 3892.27,3801.98 3891.32,3801.65 3890.47,3801.49 3895.69,3796.27 3895.84,3797.13 3896.18,3798.07 3896.64,3798.97
  region net PDM_CLK: 3816.79,3613.92 3819.62,3611.09 3820.39,3611.66 3821.3,3612.02 3822.27,3612.23 3823.25,3612.33 3818.03,3617.55 3817.93,3616.57 3817.72,3615.6 3817.36,3614.69
  region net PDM_CLK: 3829.1,3620.57 3826.27,3623.4 3825.5,3622.83 3824.59,3622.47 3823.61,3622.26 3822.64,3622.16 3827.86,3616.94 3827.96,3617.91 3828.17,3618.89 3828.53,3619.8
  region net PDM_CLK: 3861.79,3658.92 3864.62,3656.09 3865.39,3656.66 3866.3,3657.02 3867.27,3657.23 3868.25,3657.33 3863.03,3662.55 3862.93,3661.57 3862.72,3660.6 3862.36,3659.69
  region net VDD_NRF: 3799.77,3674.89 3795.59,3679.07 3794.93,3678.39 3794.26,3677.8 3793.52,3677.36 3792.64,3677.16 3797.86,3671.94 3798.06,3672.82 3798.5,3673.56 3799.09,3674.23
  region net SWO: 3527.19,3711.11 3523.19,3711.11 3523.04,3710.17 3522.66,3709.27 3522.12,3708.43 3521.5,3707.66 3528.88,3707.66 3528.26,3708.43 3527.72,3709.27 3527.33,3710.17
  region net SWO: 3844.1,3895.57 3841.27,3898.4 3840.5,3897.83 3839.59,3897.47 3838.61,3897.26 3837.64,3897.16 3842.86,3891.94 3842.96,3892.91 3843.17,3893.89 3843.53,3894.8
  region net SWO: 3766.79,3823.92 3769.62,3821.09 3770.39,3821.66 3771.3,3822.02 3772.27,3822.23 3773.25,3822.33 3768.03,3827.55 3767.93,3826.57 3767.72,3825.6 3767.36,3824.69
  region net RESET: 3615.77,3691.41 3611.77,3691.41 3611.63,3690.47 3611.25,3689.57 3610.7,3688.73 3610.08,3687.97 3617.47,3687.97 3616.84,3688.73 3616.3,3689.57 3615.92,3690.47
  region net RESET: 3736.24,3754.24 3736.24,3750.24 3737.19,3750.1 3738.09,3749.72 3738.93,3749.17 3739.69,3748.55 3739.69,3755.94 3738.93,3755.31 3738.09,3754.77 3737.19,3754.39
  region net RESET: 3929.45,3835.21 3926.62,3838.04 3926.18,3837.67 3925.74,3837.42 3925.28,3837.27 3924.81,3837.2 3924.32,3837.17 3922.64,3837.16 3927.86,3831.94 3928.03,3832.79 3928.4,3833.69 3928.9,3834.53
  region net +BATT: 3169.64,3914.21 3169.64,3918.89 3168.78,3919.01 3167.83,3919.31 3166.92,3919.75 3166.2,3920.24 3166.2,3912.86 3166.92,3913.35 3167.83,3913.79 3168.78,3914.09
  region net PIEZO_READ: 3951.6,3415.55 3951.6,3409.65 3952.55,3409.65 3953.44,3409.6 3954.28,3409.39 3955.04,3408.91 3955.04,3416.29 3954.28,3415.81 3953.44,3415.6 3952.55,3415.55
  region net GPIO2: 3748.42,3564.6 3748.42,3568.6 3747.48,3568.75 3746.58,3569.13 3745.74,3569.67 3744.98,3570.3 3744.98,3562.91 3745.74,3563.53 3746.58,3564.08 3747.48,3564.46
  region net GPIO2: 4073.44,3573.52 4073.44,3569.52 4074.38,3569.38 4075.28,3568.99 4076.12,3568.45 4076.88,3567.83 4076.88,3575.21 4076.12,3574.59 4075.28,3574.05 4074.38,3573.67
  region net RESET: 3962.15,3873.57 3964.98,3870.74 3965.75,3871.3 3966.65,3871.67 3967.63,3871.88 3968.61,3871.98 3963.39,3877.2 3963.29,3876.22 3963.08,3875.24 3962.71,3874.34
  region net SWDCLK: 3820.73,4014.99 3823.55,4012.16 3824.32,4012.72 3825.23,4013.09 3826.21,4013.3 3827.19,4013.4 3821.97,4018.62 3821.87,4017.64 3821.66,4016.66 3821.29,4015.76
  region net PDM_CLK: 3976.45,3723.48 3972.45,3723.48 3972.31,3722.54 3971.93,3721.64 3971.38,3720.8 3970.76,3720.03 3978.14,3720.03 3977.52,3720.8 3976.98,3721.64 3976.6,3722.54
  region net PDM_CLK: 4046.24,3874.24 4046.24,3870.24 4047.19,3870.1 4048.09,3869.72 4048.93,3869.17 4049.69,3868.55 4049.69,3875.94 4048.93,3875.31 4048.09,3874.77 4047.19,3874.39
  region net PDM_DATA: 3948.25,3654.12 3945.42,3656.95 3944.65,3656.39 3943.74,3656.02 3942.76,3655.81 3941.79,3655.71 3947.01,3650.49 3947.11,3651.47 3947.32,3652.45 3947.68,3653.35
  region net PDM_DATA: 4020.71,3732.24 4023.54,3729.41 4024.21,3729.98 4025.04,3730.49 4025.93,3730.86 4026.78,3731.04 4021.56,3736.26 4021.56,3734.56 4021.54,3734.07 4021.48,3733.59 4021.33,3733.14 4021.08,3732.69
  region net VDD_NRF: 3522.24,3441.8 3528.15,3441.8 3528.14,3442.75 3528.19,3443.64 3528.41,3444.48 3528.89,3445.25 3521.5,3445.25 3521.98,3444.48 3522.2,3443.64 3522.25,3442.75
  region net VDD_NRF: 3555.29,3229.07 3551.12,3224.89 3551.79,3224.23 3552.39,3223.56 3552.83,3222.82 3553.03,3221.94 3558.25,3227.16 3557.37,3227.36 3556.63,3227.8 3555.96,3228.39
  region net VDD_NRF: 3586.9,3752.76 3583.59,3756.08 3582.9,3755.55 3582,3755.09 3581.05,3754.75 3580.2,3754.59 3585.42,3749.38 3585.57,3750.23 3585.91,3751.18 3586.37,3752.07
  region net VDD_NRF: 3796.24,3794.59 3796.24,3789.9 3797.1,3789.79 3798.06,3789.48 3798.97,3789.05 3799.69,3788.55 3799.69,3795.94 3798.97,3795.44 3798.06,3795.01 3797.1,3794.7
  region net VDD_NRF: 3910.29,3604.07 3906.12,3599.89 3906.79,3599.23 3907.39,3598.56 3907.83,3597.82 3908.03,3596.94 3913.25,3602.16 3912.37,3602.36 3911.63,3602.8 3910.96,3603.39
  region net BUTTON: 3916.27,3561.09 3919.1,3563.92 3918.53,3564.69 3918.17,3565.6 3917.96,3566.57 3917.86,3567.55 3912.64,3562.33 3913.61,3562.23 3914.59,3562.02 3915.5,3561.66
  region net VDD_NRF: 3930.6,3535.54 3935.29,3535.54 3935.4,3536.41 3935.71,3537.36 3936.14,3538.27 3936.63,3538.99 3929.25,3538.99 3929.75,3538.27 3930.18,3537.36 3930.49,3536.41
  region net BUTTON: 4019.1,3467.84 4016.27,3470.67 4015.5,3470.1 4014.59,3469.74 4013.61,3469.53 4012.64,3469.43 4017.86,3464.21 4017.96,3465.19 4018.17,3466.16 4018.53,3467.07
  region net VDD_NRF: 3904.34,3440.33 3901.02,3443.64 3900.33,3443.11 3899.44,3442.65 3898.49,3442.31 3897.64,3442.16 3902.86,3436.94 3903.01,3437.79 3903.35,3438.74 3903.81,3439.63
  region net VDD_NRF: 3887.82,3778.93 3887.79,3778.08 3887.68,3777.19 3887.51,3776.27 3887.28,3775.33 3886.67,3773.41 3885.86,3771.5 3884.92,3769.64 3883.86,3767.9 3882.73,3766.35 3882.14,3765.66 3881.56,3765.03 3885.73,3760.86 3886.38,3761.38 3887.06,3761.72 3887.6,3761.71 3887.82,3761.22
  region net SWDCLK: 3667.72,4015.47 3667.21,4015.49 3666.67,4015.55 3665.5,4015.78 3664.27,4016.15 3663.02,4016.61 3661.8,4017.17 3660.68,4017.78 3659.69,4018.45 3659.26,4018.79 3658.89,4019.13 3667.96,4010.06 3667.61,4010.49 3667.38,4010.95 3667.38,4011.32 3667.72,4011.47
